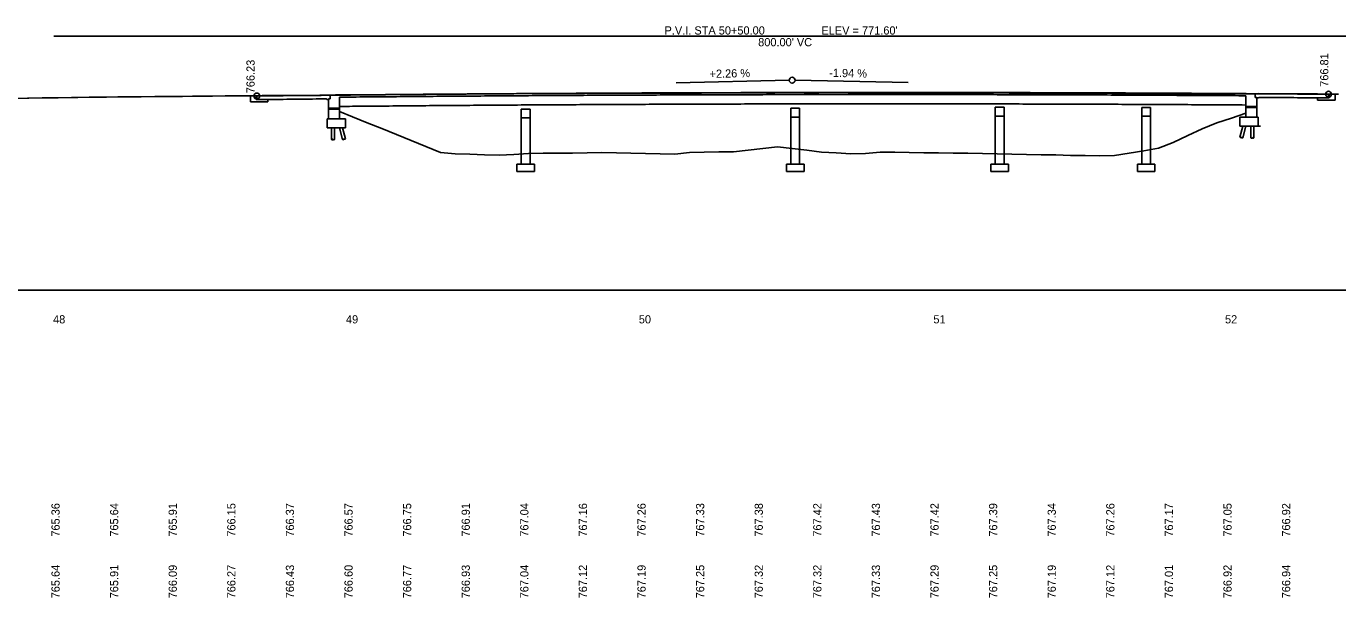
# Model space of a CAD drawing. Extents: x -209 to 3291, y 1080 to 3580.
# Drawn here: x 179.9 to 627.5, y 3225.1 to 3420.2 of the extents above; entities that cross this region are included whole.
import ezdxf

# ---------------------------------------------------------------- set-up
doc = ezdxf.new("R2010")
doc.units = 0
for name, color, linetype in [('BR_P_Gen_Approach_Slab', 7, 'Continuous'), ('BR_P_Gen_Approach_Slab_Hidden', 7, 'Continuous'), ('BR_P_Gen_Joint_Filler', 7, 'Continuous'), ('BR_P_Slab_Object', 7, 'Continuous'), ('BR_X_Sub_Foot_Object', 7, 'Continuous'), ('Default', 7, 'Continuous'), ('GK_Cells', 7, 'Continuous'), ('PF_P_Grade_Line', 7, 'Continuous'), ('PF_P_Sta_Elev_Text', 7, 'Continuous'), ('PF_P_Text', 7, 'Continuous'), ('PF_X_Ground_Line', 7, 'Continuous'), ('PF_X_Text', 7, 'Continuous')]:
    doc.layers.add(name, color=color, linetype=linetype)

msp = doc.modelspace()

# ---------------------------------------------------------------- linework, layer by layer
at = {"layer": 'BR_P_Gen_Approach_Slab'}
for p, q in [((256.35, 3396.37), (256.35, 3394.34)), ((258.57, 3396.37), (256.35, 3396.37)), ((258.35, 3396.37), (258.35, 3395.12)), ((258.57, 3395.12), (258.35, 3395.12)), ((262.36, 3394.41), (262.36, 3395.16)), ((599.83, 3395.71), (600.33, 3395.71)), ((600.33, 3395.71), (600.66, 3395.88)), ((620.54, 3395.73), (620.54, 3394.98)), ((624.33, 3395.7), (624.33, 3396.95)), ((624.33, 3396.95), (626.56, 3396.95)), ((624.55, 3396.95), (624.55, 3395.7)), ((626.56, 3396.95), (626.56, 3394.93))]:
    msp.add_line(p, q, dxfattribs=at)
for points in [[(256.35, 3394.34), (261.27, 3394.4), (262.36, 3394.41)], [(600.66, 3395.88), (601.26, 3395.87), (611.26, 3395.8), (621.26, 3395.73), (624.55, 3395.7)], [(620.54, 3394.98), (621.25, 3394.98), (626.56, 3394.93)]]:
    msp.add_spline(points, degree=3, dxfattribs=at)
at = {"layer": 'BR_P_Gen_Approach_Slab_Hidden'}
for p, q in [((258.57, 3395.12), (258.57, 3396.37)), ((282.57, 3395.2), (282.24, 3395.37)), ((282.57, 3395.2), (283.07, 3395.21)), ((283.07, 3392.21), (286.83, 3392.21)), ((599.83, 3392.78), (596.07, 3392.78))]:
    msp.add_line(p, q, dxfattribs=at)
msp.add_spline([(258.57, 3395.12), (261.26, 3395.15), (271.26, 3395.25), (281.26, 3395.36), (282.24, 3395.37)], degree=3, dxfattribs=at)
at = {"layer": 'BR_P_Gen_Joint_Filler'}
for p, q in [((286.83, 3392.21), (283.07, 3392.21)), ((283.07, 3392.21), (283.07, 3391.88)), ((283.07, 3391.88), (286.83, 3391.88)), ((286.83, 3391.88), (286.83, 3392.21)), ((596.07, 3392.44), (596.07, 3392.78)), ((596.07, 3392.78), (599.83, 3392.78)), ((599.83, 3392.44), (596.07, 3392.44)), ((599.83, 3392.78), (599.83, 3392.44))]:
    msp.add_line(p, q, dxfattribs=at)
at = {"layer": 'BR_P_Slab_Object'}
for p, q in [((283.07, 3395.37), (283.57, 3395.38)), ((283.07, 3395.37), (283.07, 3391.88)), ((283.57, 3396.63), (283.57, 3395.38)), ((286.83, 3391.88), (286.83, 3395.95)), ((596.07, 3392.44), (596.07, 3396.45)), ((599.33, 3397.13), (599.33, 3395.88)), ((599.83, 3395.88), (599.33, 3395.88)), ((599.83, 3395.88), (599.83, 3392.44))]:
    msp.add_line(p, q, dxfattribs=at)
at = {"layer": 'BR_X_Sub_Foot_Object'}
for p, q in [((283.07, 3391.88), (286.83, 3391.88)), ((283.07, 3391.88), (283.07, 3388.53)), ((286.83, 3391.88), (286.83, 3388.53)), ((348.83, 3391.88), (351.83, 3391.88)), ((348.83, 3391.88), (348.83, 3388.88)), ((348.83, 3388.88), (351.83, 3388.88)), ((348.83, 3388.88), (348.83, 3373.13)), ((351.83, 3391.88), (351.83, 3388.88)), ((351.83, 3388.88), (351.83, 3373.13)), ((440.83, 3392.18), (443.83, 3392.18)), ((440.83, 3392.18), (440.83, 3389.18)), ((440.83, 3389.18), (443.83, 3389.18)), ((440.83, 3389.18), (440.83, 3373.13)), ((443.83, 3392.18), (443.83, 3389.18)), ((443.83, 3389.18), (443.83, 3373.13)), ((510.58, 3392.51), (513.58, 3392.51)), ((510.58, 3392.51), (510.58, 3389.51)), ((510.58, 3389.51), (513.58, 3389.51)), ((510.58, 3389.51), (510.58, 3373.13)), ((513.58, 3392.51), (513.58, 3389.51)), ((513.58, 3389.51), (513.58, 3373.13)), ((560.58, 3392.46), (563.58, 3392.46)), ((560.58, 3392.46), (560.58, 3389.46)), ((560.58, 3389.46), (563.58, 3389.46)), ((560.58, 3389.46), (560.58, 3373.13)), ((563.58, 3392.46), (563.58, 3389.46)), ((563.58, 3389.46), (563.58, 3373.13)), ((594.07, 3389.1), (594.07, 3386.1)), ((600.34, 3389.1), (594.07, 3389.1)), ((596.07, 3392.44), (596.07, 3389.1)), ((599.83, 3392.44), (596.07, 3392.44)), ((599.83, 3392.44), (599.83, 3389.1)), ((600.34, 3389.1), (600.34, 3386.1)), ((282.57, 3388.53), (282.57, 3385.53)), ((282.57, 3388.53), (288.84, 3388.53)), ((282.57, 3385.53), (288.84, 3385.53)), ((282.57, 3385.53), (284.57, 3385.53)), ((284.07, 3385.53), (284.07, 3381.5)), ((284.07, 3385.53), (285.07, 3385.53)), ((285.07, 3385.53), (285.07, 3381.5)), ((286.82, 3385.53), (287.83, 3381.5)), ((286.84, 3385.53), (287.84, 3385.53)), ((287.85, 3385.53), (288.8, 3381.74)), ((288.84, 3388.53), (288.84, 3385.53)), ((600.34, 3386.1), (594.07, 3386.1)), ((595.05, 3386.1), (594.11, 3382.31)), ((596.08, 3386.1), (595.08, 3382.07)), ((598.33, 3386.1), (597.33, 3386.1)), ((597.84, 3386.1), (597.84, 3382.07)), ((600.34, 3386.1), (598.34, 3386.1)), ((598.84, 3386.1), (598.84, 3382.07)), ((601.1, 3386.1), (600.1, 3386.1)), ((347.33, 3373.13), (347.33, 3370.63)), ((347.33, 3373.13), (353.33, 3373.13)), ((353.33, 3373.13), (353.33, 3370.63)), ((439.33, 3373.13), (439.33, 3370.63)), ((439.33, 3373.13), (445.33, 3373.13)), ((445.33, 3373.13), (445.33, 3370.63)), ((509.08, 3373.13), (509.08, 3370.63)), ((509.08, 3373.13), (515.08, 3373.13)), ((515.08, 3373.13), (515.08, 3370.63)), ((559.08, 3373.13), (559.08, 3370.63)), ((559.08, 3373.13), (565.08, 3373.13)), ((565.08, 3373.13), (565.08, 3370.63)), ((347.33, 3370.63), (353.33, 3370.63)), ((439.33, 3370.63), (445.33, 3370.63)), ((509.08, 3370.63), (515.08, 3370.63)), ((559.08, 3370.63), (565.08, 3370.63))]:
    msp.add_line(p, q, dxfattribs=at)
for centre, start, end in [((284.32, 3381.29), 40.6337, 139.3663), ((284.32, 3381.72), 220.6337, 319.3663), ((284.82, 3381.72), 220.6337, 319.3663), ((288.12, 3381.35), 54.67, 153.4025), ((288.02, 3381.77), 234.67, 333.4025), ((288.5, 3381.89), 234.67, 333.4025), ((594.4, 3382.46), 206.5975, 305.33), ((594.78, 3381.92), 26.5975, 125.33), ((594.89, 3382.34), 206.5975, 305.33), ((598.09, 3382.28), 220.6337, 319.3663), ((598.59, 3381.85), 40.6337, 139.3663), ((598.59, 3382.28), 220.6337, 319.3663)]:
    msp.add_arc(centre, 0.329, start, end, dxfattribs=at)
msp.add_spline([(286.83, 3392.79), (291.26, 3392.83), (301.26, 3392.92), (311.26, 3393.01), (321.26, 3393.09), (331.26, 3393.17), (341.26, 3393.24), (351.26, 3393.3), (361.26, 3393.36), (371.26, 3393.42), (381.26, 3393.47), (391.26, 3393.51), (401.26, 3393.55), (411.26, 3393.59), (421.26, 3393.62), (431.26, 3393.64), (441.26, 3393.66), (451.26, 3393.67), (461.26, 3393.68), (471.26, 3393.69), (481.26, 3393.68), (491.26, 3393.68), (501.26, 3393.66), (511.26, 3393.64), (521.26, 3393.62), (531.26, 3393.59), (541.26, 3393.56), (551.26, 3393.52), (561.26, 3393.48), (571.26, 3393.43), (581.26, 3393.37), (591.26, 3393.31), (596.07, 3393.28)], degree=3, dxfattribs=at)
at = {"layer": 'Default'}
for p, q in [((257.57, 3396.37), (256.35, 3396.37)), ((256.35, 3396.37), (256.35, 3394.34)), ((258.35, 3395.12), (258.35, 3395.39)), ((258.57, 3395.12), (258.35, 3395.12)), ((258.57, 3396.37), (258.57, 3395.12)), ((261.19, 3395.14), (258.57, 3395.12)), ((261.26, 3395.15), (261.19, 3395.14)), ((262.36, 3395.16), (261.26, 3395.15)), ((262.36, 3394.41), (262.36, 3395.16)), ((282.24, 3395.37), (282.57, 3395.2)), ((282.57, 3395.2), (283.07, 3395.21)), ((283.07, 3395.37), (283.57, 3395.38)), ((283.57, 3395.38), (283.07, 3395.37)), ((283.07, 3395.21), (283.07, 3395.37)), ((284.95, 3396.62), (283.57, 3396.6)), ((283.57, 3395.38), (283.57, 3396.6)), ((283.57, 3396.6), (283.57, 3395.38)), ((285.09, 3396.64), (284.95, 3396.62)), ((599.33, 3397.13), (599.15, 3397.14)), ((599.33, 3397.04), (599.33, 3397.13)), ((599.33, 3397.04), (599.33, 3395.88)), ((599.33, 3395.88), (599.33, 3397.04)), ((599.33, 3395.88), (599.83, 3395.88)), ((599.83, 3395.88), (599.33, 3395.88)), ((599.83, 3395.88), (599.83, 3395.71)), ((599.83, 3395.71), (600.33, 3395.71)), ((600.33, 3395.71), (600.66, 3395.88)), ((621.26, 3395.73), (620.54, 3395.73)), ((620.54, 3395.73), (620.54, 3394.98)), ((624.33, 3395.7), (624.33, 3395.95)), ((624.55, 3395.98), (624.55, 3395.7)), ((625.74, 3396.95), (625.33, 3396.95)), ((626.56, 3396.95), (625.74, 3396.95)), ((626.56, 3394.93), (626.56, 3396.95)), ((283.07, 3392.21), (286.83, 3392.21)), ((596.07, 3392.78), (599.83, 3392.78))]:
    msp.add_line(p, q, dxfattribs=at)
for points in [[(283.57, 3396.6), (280.55, 3396.55), (277.11, 3396.56)], [(283.07, 3395.37), (283.07, 3395.21), (283.07, 3392.21)], [(286.83, 3392.21), (286.83, 3392.79), (286.83, 3395.95)], [(300.38, 3396.79), (300.37, 3396.79), (300.35, 3396.79)], [(337.66, 3397.09), (335.37, 3397.06), (334.38, 3397.06)], [(599.15, 3397.14), (595.37, 3397.04), (590.37, 3397.05), (585.37, 3397.07), (580.37, 3397.1), (575.37, 3397.13), (570.37, 3397.15), (565.37, 3397.18), (560.37, 3397.2), (555.37, 3397.23), (550.37, 3397.26), (545.37, 3397.28), (540.37, 3397.29), (535.37, 3397.32), (530.37, 3397.33), (525.37, 3397.34), (520.37, 3397.37), (515.37, 3397.38), (510.37, 3397.39), (505.37, 3397.4), (500.37, 3397.41), (495.37, 3397.42), (490.37, 3397.42), (485.37, 3397.44), (480.37, 3397.45), (475.37, 3397.45), (470.37, 3397.47), (465.37, 3397.46), (460.37, 3397.45), (455.37, 3397.51), (450.37, 3397.44), (445.37, 3397.43), (440.37, 3397.5), (435.37, 3397.45), (430.37, 3397.45), (425.37, 3397.42), (420.37, 3397.39), (415.37, 3397.41), (410.37, 3397.38), (405.37, 3397.35), (400.37, 3397.36), (395.37, 3397.32), (390.37, 3397.32), (385.37, 3397.32), (380.37, 3397.28), (375.37, 3397.29), (370.37, 3397.25), (365.37, 3397.22), (360.37, 3397.22), (355.37, 3397.2), (350.37, 3397.16), (348.01, 3397.16)], [(596.07, 3396.45), (596.07, 3393.28), (596.07, 3392.78)], [(606.81, 3397.08), (603.38, 3397.09), (602.04, 3397.09), (599.59, 3397.07), (599.52, 3397.04), (599.33, 3397.04)], [(599.83, 3392.78), (599.83, 3395.71), (599.83, 3395.88)]]:
    msp.add_lwpolyline(points, dxfattribs=at)
for centre, start, end in [((258.57, 3396.37), 180, 257.3305), ((624.33, 3396.95), 179.544, 270), ((624.33, 3396.95), 282.6695, 0)]:
    msp.add_arc(centre, 1, start, end, dxfattribs=at)
for points in [[(256.35, 3394.34), (261.27, 3394.4), (262.36, 3394.41)], [(277.11, 3396.56), (271.26, 3396.5), (261.26, 3396.4), (258.57, 3396.37)], [(258.57, 3395.12), (261.26, 3395.15), (271.26, 3395.25), (281.26, 3395.36), (282.24, 3395.37)], [(300.35, 3396.79), (291.26, 3396.7), (285.09, 3396.64)], [(286.83, 3395.95), (291.26, 3396), (301.26, 3396.09), (311.26, 3396.17), (321.26, 3396.26), (331.26, 3396.33), (341.26, 3396.4), (351.26, 3396.47), (361.26, 3396.53), (371.26, 3396.59), (381.26, 3396.64), (391.26, 3396.68), (401.26, 3396.72), (411.26, 3396.76), (421.26, 3396.78), (431.26, 3396.81), (441.26, 3396.83), (451.26, 3396.84), (461.26, 3396.85), (471.26, 3396.85), (481.26, 3396.85), (491.26, 3396.84), (501.26, 3396.83), (511.26, 3396.81), (521.26, 3396.79), (531.26, 3396.76), (541.26, 3396.73), (551.26, 3396.69), (561.26, 3396.64), (571.26, 3396.59), (581.26, 3396.54), (591.26, 3396.48), (596.07, 3396.45)], [(334.38, 3397.06), (331.26, 3397.04), (321.26, 3396.96), (311.26, 3396.88), (301.26, 3396.8), (300.38, 3396.79)], [(348.01, 3397.16), (341.26, 3397.11), (337.66, 3397.09)], [(600.66, 3395.88), (601.26, 3395.87), (611.26, 3395.8), (621.26, 3395.73), (624.33, 3395.7)], [(623.33, 3396.96), (621.26, 3396.98), (611.26, 3397.05), (606.81, 3397.08)], [(620.54, 3394.98), (621.25, 3394.98), (626.56, 3394.93)]]:
    msp.add_spline(points, degree=3, dxfattribs=at)
msp.add_open_spline([(624.55, 3395.7), (623.45, 3395.71), (622.36, 3395.72), (621.26, 3395.73)], degree=2, dxfattribs=at)
at = {"layer": 'GK_Cells'}
msp.add_line((-8.74, 3330.13), (3291.26, 3330.13), dxfattribs=at)
at = {"layer": 'PF_P_Grade_Line'}
for points in [[(258.57, 3396.37), (261.26, 3396.4), (271.26, 3396.5), (281.26, 3396.61), (291.26, 3396.7), (301.26, 3396.8), (311.26, 3396.88), (321.26, 3396.96), (331.26, 3397.04), (341.26, 3397.11), (351.26, 3397.18), (361.26, 3397.24), (371.26, 3397.29), (381.26, 3397.34), (391.26, 3397.39), (401.26, 3397.43), (411.26, 3397.46), (421.26, 3397.49), (431.26, 3397.52), (441.26, 3397.54), (451.26, 3397.55), (461.26, 3397.56), (471.26, 3397.56), (481.26, 3397.56), (491.26, 3397.55), (501.26, 3397.54), (511.26, 3397.52), (521.26, 3397.5), (531.26, 3397.47), (541.26, 3397.43), (551.26, 3397.4), (561.26, 3397.35), (571.26, 3397.3), (581.26, 3397.25), (591.26, 3397.19), (601.26, 3397.12), (611.26, 3397.05), (621.26, 3396.98), (624.33, 3396.95)], [(286.83, 3395.95), (291.26, 3396), (301.26, 3396.09), (311.26, 3396.17), (321.26, 3396.26), (331.26, 3396.33), (341.26, 3396.4), (351.26, 3396.47), (361.26, 3396.53), (371.26, 3396.59), (381.26, 3396.64), (391.26, 3396.68), (401.26, 3396.72), (411.26, 3396.76), (421.26, 3396.78), (431.26, 3396.81), (441.26, 3396.83), (451.26, 3396.84), (461.26, 3396.85), (471.26, 3396.85), (481.26, 3396.85), (491.26, 3396.84), (501.26, 3396.83), (511.26, 3396.81), (521.26, 3396.79), (531.26, 3396.76), (541.26, 3396.73), (551.26, 3396.69), (561.26, 3396.64), (571.26, 3396.59), (581.26, 3396.54), (591.26, 3396.48), (596.07, 3396.45)]]:
    msp.add_spline(points, degree=3, dxfattribs=at)
at = {"layer": 'PF_P_Text'}
for p, q in [((189.31, 3416.73), (693.33, 3416.73)), ((401.67, 3400.84), (440.26, 3401.71)), ((480.85, 3400.97), (442.26, 3401.71))]:
    msp.add_line(p, q, dxfattribs=at)
for centre in [(441.26, 3401.73), (624.33, 3396.95), (258.57, 3396.37)]:
    msp.add_circle(centre, 1, dxfattribs=at)
at = {"layer": 'PF_X_Ground_Line'}
msp.add_line((284.95, 3396.62), (285.37, 3396.7), dxfattribs=at)
for points in [[(175.7, 3395.53), (180.26, 3395.6), (180.7, 3395.61), (185.27, 3395.68), (185.7, 3395.68), (190.28, 3395.76), (190.7, 3395.76), (195.29, 3395.83), (195.7, 3395.84), (197.46, 3395.88), (201.34, 3395.94), (203.3, 3395.97), (207.22, 3396.01), (211.17, 3396.04), (213.17, 3396.05), (213.55, 3396.05), (218.17, 3396.09), (219.06, 3396.12), (223.77, 3396.19), (224.57, 3396.19), (225.4, 3396.2), (227.98, 3396.2), (232.46, 3396.24), (233.17, 3396.23), (236.6, 3396.29), (239.2, 3396.31), (241.84, 3396.33), (243.39, 3396.33), (247.76, 3396.37), (252.15, 3396.41), (253.43, 3396.43), (257.85, 3396.44), (259.15, 3396.46), (259.29, 3396.46), (260.35, 3396.48), (262.71, 3396.53), (263.66, 3396.54), (265.83, 3396.56), (276.61, 3396.57), (280.55, 3396.55), (284.95, 3396.62)], [(285.37, 3396.7), (285.37, 3396.7), (285.37, 3396.7), (290.37, 3396.73), (295.37, 3396.76), (300.37, 3396.79), (305.37, 3396.85), (310.37, 3396.9), (315.37, 3396.94), (320.37, 3396.98), (325.37, 3397.02), (330.37, 3397.06), (335.37, 3397.06), (340.37, 3397.11), (345.37, 3397.15), (350.37, 3397.16), (355.37, 3397.2), (360.37, 3397.22), (365.37, 3397.22), (370.37, 3397.25), (375.37, 3397.29), (380.37, 3397.28), (385.37, 3397.32), (390.37, 3397.32), (395.37, 3397.32), (400.37, 3397.36), (405.37, 3397.35), (410.37, 3397.38), (415.37, 3397.41), (420.37, 3397.39), (425.37, 3397.42), (430.37, 3397.45), (435.37, 3397.45), (440.37, 3397.5), (445.37, 3397.43), (450.37, 3397.44), (455.37, 3397.51), (460.37, 3397.45), (465.37, 3397.46), (470.37, 3397.47), (475.37, 3397.45), (480.37, 3397.45), (485.37, 3397.44), (490.37, 3397.42), (495.37, 3397.42), (500.37, 3397.41), (505.37, 3397.4), (510.37, 3397.39), (515.37, 3397.38), (520.37, 3397.37), (525.37, 3397.34), (530.37, 3397.33), (535.37, 3397.32), (540.37, 3397.29), (545.37, 3397.28), (550.37, 3397.26), (555.37, 3397.23), (560.37, 3397.2), (565.37, 3397.18), (570.37, 3397.15), (575.37, 3397.13), (580.37, 3397.1), (585.37, 3397.07), (590.37, 3397.05), (595.37, 3397.04), (600.37, 3397.17), (600.37, 3397.17)], [(598.65, 3397.04), (599.52, 3397.04), (599.59, 3397.07), (602.04, 3397.09), (603.38, 3397.09), (611.08, 3397.08), (611.64, 3397.07), (620.52, 3397.06), (622.66, 3397.03), (624.49, 3396.98), (625.57, 3396.95), (627.69, 3396.94)], [(286.83, 3391.12), (291.26, 3389.29), (296.26, 3387.25), (301.26, 3385.21), (306.26, 3383.16), (311.26, 3381.12), (316.26, 3379.07), (321.26, 3377.03), (326.26, 3376.64), (331.26, 3376.47), (336.26, 3376.29), (341.26, 3376.11), (346.26, 3376.34), (351.26, 3376.7), (356.26, 3376.79), (361.26, 3376.79), (366.26, 3376.81), (371.26, 3376.95), (376.26, 3377.08), (381.26, 3376.97), (386.26, 3376.85), (391.26, 3376.73), (396.26, 3376.62), (401.26, 3376.51), (406.26, 3377.06), (411.26, 3377.23), (416.26, 3377.26), (421.26, 3377.3), (426.26, 3377.86), (431.26, 3378.42), (436.26, 3378.97), (441.26, 3378.43), (446.26, 3377.83), (451.26, 3377.24), (456.26, 3376.94), (461.26, 3376.64), (466.26, 3376.78), (471.26, 3377.14), (476.26, 3377.2), (481.26, 3377.06), (486.26, 3377.01), (491.26, 3376.94), (496.26, 3376.86), (501.26, 3376.79), (506.26, 3376.7), (511.26, 3376.61), (516.26, 3376.52), (521.26, 3376.43), (526.26, 3376.33), (531.26, 3376.22), (536.26, 3376.09), (541.26, 3376.03), (546.26, 3375.97), (551.26, 3376.05), (556.26, 3376.87), (561.26, 3377.69), (566.26, 3378.51), (571.26, 3380.53), (576.26, 3382.86), (581.26, 3385.19), (586.26, 3387.14), (591.26, 3388.83), (596.07, 3390.45)]]:
    msp.add_lwpolyline(points, dxfattribs=at)

# ---------------------------------------------------------------- texts
at = {"layer": 'PF_P_Sta_Elev_Text'}
for s, p in [('48', (189.02, 3318.73)), ('48', (189.02, 3318.73)), ('49', (288.98, 3318.73)), ('49', (288.98, 3318.73)), ('49', (288.98, 3318.73)), ('50', (388.93, 3318.73)), ('50', (388.93, 3318.73)), ('50', (388.93, 3318.73)), ('51', (489.46, 3318.73)), ('51', (489.46, 3318.73)), ('51', (489.46, 3318.73)), ('52', (589, 3318.73)), ('52', (589, 3318.73)), ('52', (589, 3318.73))]:
    msp.add_text(s, height=2.8, dxfattribs=at).set_placement(p)
at = {"layer": 'PF_P_Text'}
for s, p in [('P.V.I. STA 50+50.00', (397.7, 3417.33)), ("ELEV = 771.60'", (451.26, 3417.33)), ("800.00' VC", (429.67, 3413.33))]:
    msp.add_text(s, height=2.8, dxfattribs=at).set_placement(p)
for s, rotation, p in [('766.23', 90, (257.81, 3397.29)), ('766.81', 90, (624.28, 3399.5)), ('+2.26 %', 1.2947, (413.1, 3402.5)), ('-1.94 %', 358.89, (453.88, 3402.89)), ('765.36', 90, (191.26, 3245.93)), ('765.64', 90, (211.26, 3245.93)), ('765.91', 90, (231.26, 3245.93)), ('766.15', 90, (251.26, 3245.93)), ('766.37', 90, (271.26, 3245.93)), ('766.57', 90, (291.26, 3245.93)), ('766.75', 90, (311.26, 3245.93)), ('766.91', 90, (331.26, 3245.93)), ('767.04', 90, (351.26, 3245.93)), ('767.16', 90, (371.26, 3245.93)), ('767.26', 90, (391.26, 3245.93)), ('767.33', 90, (411.26, 3245.93)), ('767.38', 90, (431.26, 3245.93)), ('767.42', 90, (451.26, 3245.93)), ('767.43', 90, (471.26, 3245.93)), ('767.42', 90, (491.26, 3245.93)), ('767.39', 90, (511.26, 3245.93)), ('767.34', 90, (531.26, 3245.93)), ('767.26', 90, (551.26, 3245.93)), ('767.17', 90, (571.26, 3245.93)), ('767.05', 90, (591.26, 3245.93)), ('766.92', 90, (611.26, 3245.93))]:
    msp.add_text(s, height=2.8, rotation=rotation, dxfattribs=at).set_placement(p)
at = {"layer": 'PF_X_Text'}
for s, p in [('765.64', (191.26, 3224.88)), ('765.91', (211.26, 3224.88)), ('766.09', (231.26, 3224.88)), ('766.27', (251.26, 3224.88)), ('766.43', (271.26, 3224.88)), ('766.60', (291.26, 3224.88)), ('766.77', (311.26, 3224.88)), ('766.93', (331.26, 3224.88)), ('767.04', (351.26, 3224.88)), ('767.12', (371.26, 3224.88)), ('767.19', (391.26, 3224.88)), ('767.25', (411.26, 3224.88)), ('767.32', (431.26, 3224.88)), ('767.32', (451.26, 3224.88)), ('767.33', (471.26, 3224.88)), ('767.29', (491.26, 3224.88)), ('767.25', (511.26, 3224.88)), ('767.19', (531.26, 3224.88)), ('767.12', (551.26, 3224.88)), ('767.01', (571.26, 3224.88)), ('766.92', (591.26, 3224.88)), ('766.94', (611.26, 3224.88))]:
    msp.add_text(s, height=2.8, rotation=90, dxfattribs=at).set_placement(p)

doc.saveas('drawing.dxf')
